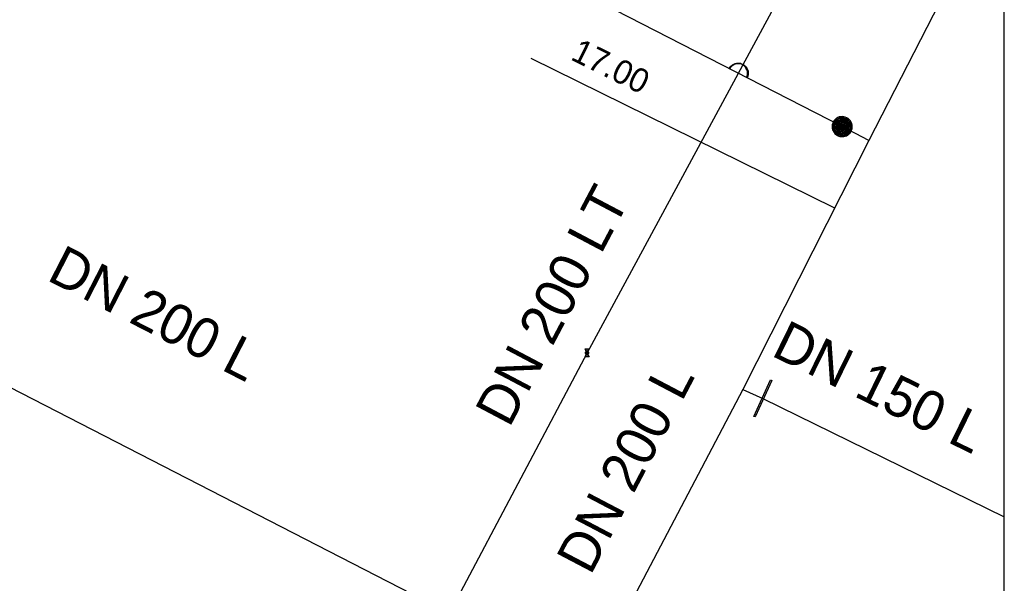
# Model space of a CAD drawing. Extents: x -820257 to -819974, y -1070894 to -1070484.
# Drawn here: x -820024.86 to -819975.6, y -1070605.59 to -1070577.38 of the extents above; entities that cross this region are included whole.
import ezdxf

# ---------------------------------------------------------------- set-up
doc = ezdxf.new("R2010")
doc.units = 0
for name, color, linetype in [('Default', 7, 'Continuous'), ('Lomový bod vodovodu', 7, 'Continuous'), ('Nepropojené křížení vodovodu', 7, 'Continuous'), ('Oměrka vodovodu', 7, 'Continuous'), ('Oměrka-text', 7, 'Continuous'), ('Přípojka vodovodu', 7, 'Continuous'), ('Přípojkový uzávěr', 7, 'Continuous'), ('Roz-řad', 7, 'Continuous'), ('Roz-řad-popis základní', 7, 'Continuous'), ('Řad-šoupě', 7, 'Continuous')]:
    doc.layers.add(name, color=color, linetype=linetype)

msp = doc.modelspace()

# ---------------------------------------------------------------- linework, layer by layer
at = {"layer": 'Default'}
msp.add_line((-819975.603, -1070893.932), (-819975.603, -1070484.403), dxfattribs=at)
at = {"layer": 'Lomový bod vodovodu'}
for points in [[(-819996.518, -1070593.986), (-819996.58, -1070593.85), (-819996.38, -1070593.85), (-819996.443, -1070593.986)], [(-819996.443, -1070594.114), (-819996.38, -1070594.25), (-819996.58, -1070594.25), (-819996.518, -1070594.114)], [(-819996.458, -1070593.979), (-819996.404, -1070593.863), (-819996.558, -1070593.863), (-819996.503, -1070593.979)], [(-819996.503, -1070594.121), (-819996.558, -1070594.238), (-819996.404, -1070594.238), (-819996.458, -1070594.121)], [(-819996.512, -1070594.103), (-819996.488, -1070594.05), (-819996.512, -1070593.997)], [(-819996.498, -1070593.99), (-819996.48, -1070594.028), (-819996.463, -1070593.99)], [(-819996.463, -1070594.11), (-819996.48, -1070594.072), (-819996.498, -1070594.11)], [(-819996.448, -1070593.997), (-819996.472, -1070594.05), (-819996.448, -1070594.103)]]:
    msp.add_lwpolyline(points, dxfattribs=at)
for points in [[(-819996.518, -1070594.114), (-819996.535, -1070594.105), (-819996.545, -1070594.087), (-819996.555, -1070594.07), (-819996.555, -1070594.05), (-819996.555, -1070594.03), (-819996.545, -1070594.013), (-819996.535, -1070593.995), (-819996.518, -1070593.986)], [(-819996.512, -1070593.997), (-819996.526, -1070594.005), (-819996.534, -1070594.019), (-819996.542, -1070594.034), (-819996.542, -1070594.05), (-819996.542, -1070594.066), (-819996.534, -1070594.081), (-819996.526, -1070594.095), (-819996.512, -1070594.103)], [(-819996.503, -1070593.979), (-819996.492, -1070593.975), (-819996.48, -1070593.975), (-819996.469, -1070593.975), (-819996.458, -1070593.979)], [(-819996.458, -1070594.121), (-819996.468, -1070594.125), (-819996.48, -1070594.125), (-819996.492, -1070594.125), (-819996.503, -1070594.121)], [(-819996.463, -1070593.99), (-819996.471, -1070593.988), (-819996.48, -1070593.988), (-819996.489, -1070593.988), (-819996.498, -1070593.99)], [(-819996.498, -1070594.11), (-819996.489, -1070594.112), (-819996.48, -1070594.112), (-819996.471, -1070594.112), (-819996.463, -1070594.11)], [(-819996.448, -1070594.103), (-819996.434, -1070594.095), (-819996.426, -1070594.081), (-819996.418, -1070594.066), (-819996.418, -1070594.05), (-819996.418, -1070594.034), (-819996.426, -1070594.019), (-819996.434, -1070594.005), (-819996.448, -1070593.997)], [(-819996.443, -1070593.986), (-819996.425, -1070593.995), (-819996.415, -1070594.013), (-819996.405, -1070594.03), (-819996.405, -1070594.05), (-819996.405, -1070594.07), (-819996.415, -1070594.087), (-819996.425, -1070594.105), (-819996.443, -1070594.114)]]:
    msp.add_open_spline(points, degree=3, dxfattribs=at)
at = {"layer": 'Nepropojené křížení vodovodu'}
for points in [[(-819989.337, -1070579.841), (-819989.365, -1070579.826)], [(-819988.476, -1070580.284), (-819988.504, -1070580.269)]]:
    msp.add_lwpolyline(points, dxfattribs=at)
for points in [[(-819989.365, -1070579.826), (-819989.305, -1070579.71), (-819989.191, -1070579.634), (-819989.076, -1070579.558), (-819988.94, -1070579.555), (-819988.805, -1070579.552), (-819988.692, -1070579.61), (-819988.58, -1070579.668), (-819988.503, -1070579.78), (-819988.426, -1070579.892), (-819988.421, -1070580.029), (-819988.416, -1070580.168), (-819988.476, -1070580.284)], [(-819988.504, -1070580.269), (-819988.447, -1070580.16), (-819988.453, -1070580.031), (-819988.458, -1070579.902), (-819988.53, -1070579.797), (-819988.601, -1070579.692), (-819988.706, -1070579.638), (-819988.812, -1070579.584), (-819988.939, -1070579.586), (-819989.067, -1070579.589), (-819989.174, -1070579.66), (-819989.281, -1070579.732), (-819989.337, -1070579.841)]]:
    msp.add_open_spline(points, degree=3, dxfattribs=at)
at = {"layer": 'Oměrka vodovodu'}
msp.add_line((-819999.288, -1070579.3), (-819984.092, -1070586.802), dxfattribs=at)
at = {"layer": 'Přípojka vodovodu'}
msp.add_lwpolyline([(-819982.38, -1070583.418), (-819983.714, -1070582.732), (-820002.391, -1070573.129)], dxfattribs=at)
at = {"layer": 'Přípojkový uzávěr'}
for points in [[(-819983.486, -1070582.287), (-819983.373, -1070582.345), (-819983.297, -1070582.457), (-819983.22, -1070582.569), (-819983.215, -1070582.707), (-819983.209, -1070582.845), (-819983.269, -1070582.961), (-819983.329, -1070583.077), (-819983.442, -1070583.152), (-819983.555, -1070583.228), (-819983.691, -1070583.232), (-819983.827, -1070583.236), (-819983.943, -1070583.176), (-819984.058, -1070583.117), (-819984.134, -1070583.004), (-819984.209, -1070582.891), (-819984.214, -1070582.755), (-819984.218, -1070582.619), (-819984.159, -1070582.504), (-819984.099, -1070582.387), (-819983.984, -1070582.311), (-819983.869, -1070582.235), (-819983.734, -1070582.232), (-819983.598, -1070582.229), (-819983.486, -1070582.287)], [(-819983.507, -1070582.329), (-819983.609, -1070582.277), (-819983.732, -1070582.279), (-819983.855, -1070582.281), (-819983.959, -1070582.35), (-819984.063, -1070582.42), (-819984.117, -1070582.525), (-819984.171, -1070582.63), (-819984.167, -1070582.753), (-819984.163, -1070582.876), (-819984.094, -1070582.978), (-819984.026, -1070583.081), (-819983.921, -1070583.135), (-819983.816, -1070583.189), (-819983.693, -1070583.185), (-819983.569, -1070583.181), (-819983.467, -1070583.113), (-819983.365, -1070583.044), (-819983.311, -1070582.94), (-819983.257, -1070582.834), (-819983.262, -1070582.709), (-819983.266, -1070582.584), (-819983.336, -1070582.482), (-819983.405, -1070582.381), (-819983.507, -1070582.329)], [(-819983.523, -1070582.359), (-819983.428, -1070582.408), (-819983.364, -1070582.501), (-819983.3, -1070582.595), (-819983.296, -1070582.711), (-819983.291, -1070582.826), (-819983.341, -1070582.924), (-819983.391, -1070583.021), (-819983.486, -1070583.084), (-819983.58, -1070583.148), (-819983.694, -1070583.151), (-819983.808, -1070583.154), (-819983.906, -1070583.104), (-819984.002, -1070583.055), (-819984.066, -1070582.96), (-819984.13, -1070582.865), (-819984.133, -1070582.751), (-819984.136, -1070582.638), (-819984.087, -1070582.541), (-819984.036, -1070582.443), (-819983.94, -1070582.379), (-819983.844, -1070582.315), (-819983.73, -1070582.313), (-819983.616, -1070582.311), (-819983.523, -1070582.359)], [(-819983.543, -1070582.398), (-819983.682, -1070582.327), (-819983.829, -1070582.374), (-819983.976, -1070582.422), (-819984.047, -1070582.561), (-819984.118, -1070582.699), (-819984.071, -1070582.847), (-819984.023, -1070582.994), (-819983.886, -1070583.065), (-819983.747, -1070583.136), (-819983.599, -1070583.089), (-819983.451, -1070583.042), (-819983.38, -1070582.904), (-819983.309, -1070582.765), (-819983.356, -1070582.618), (-819983.403, -1070582.47), (-819983.543, -1070582.398)], [(-819983.564, -1070582.439), (-819983.442, -1070582.502), (-819983.401, -1070582.631), (-819983.36, -1070582.76), (-819983.422, -1070582.881), (-819983.485, -1070583.002), (-819983.614, -1070583.043), (-819983.743, -1070583.085), (-819983.864, -1070583.022), (-819983.986, -1070582.96), (-819984.027, -1070582.831), (-819984.068, -1070582.702), (-819984.006, -1070582.581), (-819983.944, -1070582.459), (-819983.815, -1070582.418), (-819983.686, -1070582.376), (-819983.564, -1070582.439)], [(-819983.582, -1070582.474), (-819983.689, -1070582.419), (-819983.803, -1070582.456), (-819983.916, -1070582.492), (-819983.971, -1070582.599), (-819984.025, -1070582.705), (-819983.989, -1070582.819), (-819983.953, -1070582.932), (-819983.846, -1070582.987), (-819983.74, -1070583.042), (-819983.626, -1070583.005), (-819983.512, -1070582.969), (-819983.457, -1070582.863), (-819983.403, -1070582.756), (-819983.439, -1070582.643), (-819983.475, -1070582.529), (-819983.582, -1070582.474)], [(-819983.6, -1070582.509), (-819983.506, -1070582.557), (-819983.475, -1070582.656), (-819983.444, -1070582.754), (-819983.492, -1070582.847), (-819983.539, -1070582.939), (-819983.637, -1070582.97), (-819983.736, -1070583.002), (-819983.828, -1070582.954), (-819983.92, -1070582.907), (-819983.952, -1070582.809), (-819983.984, -1070582.71), (-819983.936, -1070582.618), (-819983.889, -1070582.526), (-819983.791, -1070582.494), (-819983.693, -1070582.462), (-819983.6, -1070582.509)], [(-819983.621, -1070582.551), (-819983.696, -1070582.512), (-819983.776, -1070582.538), (-819983.856, -1070582.563), (-819983.895, -1070582.638), (-819983.933, -1070582.714), (-819983.908, -1070582.793), (-819983.882, -1070582.873), (-819983.807, -1070582.912), (-819983.732, -1070582.95), (-819983.652, -1070582.925), (-819983.572, -1070582.899), (-819983.533, -1070582.824), (-819983.495, -1070582.749), (-819983.52, -1070582.669), (-819983.546, -1070582.589), (-819983.621, -1070582.551)], [(-819983.637, -1070582.581), (-819983.574, -1070582.614), (-819983.553, -1070582.68), (-819983.532, -1070582.746), (-819983.564, -1070582.808), (-819983.596, -1070582.871), (-819983.663, -1070582.892), (-819983.729, -1070582.913), (-819983.791, -1070582.881), (-819983.853, -1070582.849), (-819983.875, -1070582.783), (-819983.896, -1070582.717), (-819983.864, -1070582.654), (-819983.832, -1070582.592), (-819983.765, -1070582.571), (-819983.699, -1070582.549), (-819983.637, -1070582.581)], [(-819983.657, -1070582.621), (-819983.703, -1070582.597), (-819983.752, -1070582.613), (-819983.801, -1070582.629), (-819983.825, -1070582.675), (-819983.849, -1070582.721), (-819983.833, -1070582.77), (-819983.817, -1070582.819), (-819983.771, -1070582.843), (-819983.725, -1070582.867), (-819983.676, -1070582.851), (-819983.626, -1070582.835), (-819983.603, -1070582.789), (-819983.579, -1070582.743), (-819983.594, -1070582.694), (-819983.61, -1070582.645), (-819983.657, -1070582.621)], [(-819983.678, -1070582.662), (-819983.649, -1070582.677), (-819983.639, -1070582.708), (-819983.629, -1070582.738), (-819983.645, -1070582.767), (-819983.659, -1070582.796), (-819983.69, -1070582.806), (-819983.72, -1070582.816), (-819983.75, -1070582.801), (-819983.779, -1070582.786), (-819983.788, -1070582.756), (-819983.798, -1070582.725), (-819983.784, -1070582.696), (-819983.768, -1070582.666), (-819983.738, -1070582.657), (-819983.707, -1070582.648), (-819983.678, -1070582.662)], [(-819983.693, -1070582.69), (-819983.71, -1070582.681), (-819983.728, -1070582.687), (-819983.747, -1070582.693), (-819983.756, -1070582.71), (-819983.765, -1070582.728), (-819983.759, -1070582.746), (-819983.753, -1070582.765), (-819983.736, -1070582.773), (-819983.718, -1070582.783), (-819983.7, -1070582.777), (-819983.681, -1070582.771), (-819983.672, -1070582.753), (-819983.663, -1070582.735), (-819983.669, -1070582.717), (-819983.675, -1070582.699), (-819983.693, -1070582.69)]]:
    msp.add_open_spline(points, degree=3, dxfattribs=at)
at = {"layer": 'Roz-řad'}
for p, q in [((-820030.723, -1070593.018), (-819996.078, -1070610.817)), ((-819988.683, -1070595.88), (-819987.687, -1070596.335))]:
    msp.add_line(p, q, dxfattribs=at)
for points in [[(-819975.603, -1070555.156), (-819980.6, -1070564.65), (-819996.48, -1070594.05), (-820003.11, -1070606.6), (-820007.73, -1070614.37), (-820021.61, -1070627.51)], [(-819975.603, -1070570.213), (-819982.38, -1070583.418), (-819988.683, -1070595.88)], [(-819988.683, -1070595.88), (-819995.039, -1070607.985), (-819995.774, -1070609.367)], [(-819987.687, -1070596.335), (-819975.603, -1070602.258)]]:
    msp.add_lwpolyline(points, dxfattribs=at)
at = {"layer": 'Řad-šoupě'}
msp.add_lwpolyline([(-819987.242, -1070595.437), (-819988.073, -1070597.256), (-819988.13, -1070597.23), (-819987.299, -1070595.411), (-819987.242, -1070595.437)], dxfattribs=at)

# ---------------------------------------------------------------- texts
at = {"layer": 'Oměrka-text'}
msp.add_text('17.00', height=1.2, rotation=333.7253, dxfattribs=at).set_placement((-819997.352, -1070579.353))
at = {"layer": 'Roz-řad-popis základní'}
for s, rotation, p in [('DN 200 LT', 62.1531, (-820000.372, -1070597.845)), ('DN 200 L', 332.808, (-820023.567, -1070590.381)), ('DN 150 L', 333.8875, (-819987.323, -1070594.168)), ('DN 200 L', 62.2973, (-819996.306, -1070605.23))]:
    msp.add_text(s, height=2, rotation=rotation, dxfattribs=at).set_placement(p)

doc.saveas('drawing.dxf')
